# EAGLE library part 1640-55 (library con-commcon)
COMPACT PCI TYPE C - 55 PINS 2mm HARD METRIC SOCKETS
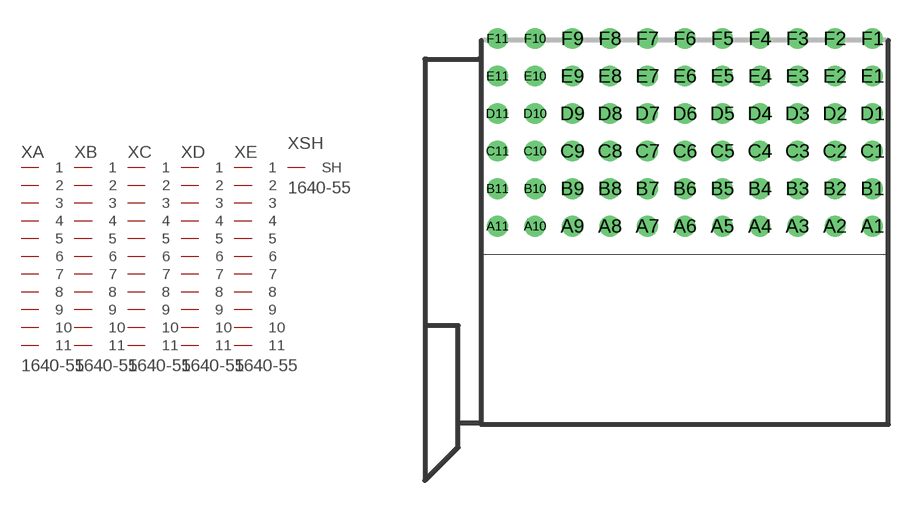
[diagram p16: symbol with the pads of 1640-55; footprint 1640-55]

Designator prefix X; gates A=PIN11 B=PIN11 C=PIN11 D=PIN11 E=PIN11 SH=SHIELD

## 1640-55 (OC_FARNELL: unknown; OC_NEWARK: unknown)  [1640-55]
A1  A:1  pas
A2  A:2  pas
A3  A:3  pas
A4  A:4  pas
A5  A:5  pas
A6  A:6  pas
A7  A:7  pas
A8  A:8  pas
A9  A:9  pas
A10  A:10  pas
A11  A:11  pas
B1  B:1  pas
B2  B:2  pas
B3  B:3  pas
B4  B:4  pas
B5  B:5  pas
B6  B:6  pas
B7  B:7  pas
B8  B:8  pas
B9  B:9  pas
B10  B:10  pas
B11  B:11  pas
C1  C:1  pas
C2  C:2  pas
C3  C:3  pas
C4  C:4  pas
C5  C:5  pas
C6  C:6  pas
C7  C:7  pas
C8  C:8  pas
C9  C:9  pas
C10  C:10  pas
C11  C:11  pas
D1  D:1  pas
D2  D:2  pas
D3  D:3  pas
D4  D:4  pas
D5  D:5  pas
D6  D:6  pas
D7  D:7  pas
D8  D:8  pas
D9  D:9  pas
D10  D:10  pas
D11  D:11  pas
E1  E:1  pas
E2  E:2  pas
E3  E:3  pas
E4  E:4  pas
E5  E:5  pas
E6  E:6  pas
E7  E:7  pas
E8  E:8  pas
E9  E:9  pas
E10  E:10  pas
E11  E:11  pas
F1  SH:SH  pas

## Footprint 1640-55 (pad centres in mm)
COMPACT PCI TYPE C - 55 PINS 2mm HARD METRIC SOCKETS
drill 0.6 round: A1 10,1.27; A2 8,1.27; A3 6,1.27; A4 4,1.27; A5 2,1.27; A6 0,1.27; A7 -2,1.27; A8 -4,1.27; A9 -6,1.27; A10 -8,1.27; A11 -10,1.27; B1 10,3.27; B2 8,3.27; B3 6,3.27; B4 4,3.27; B5 2,3.27; B6 0,3.27; B7 -2,3.27; B8 -4,3.27; B9 -6,3.27; B10 -8,3.27; B11 -10,3.27; C1 10,5.27; C2 8,5.27; C3 6,5.27; C4 4,5.27; C5 2,5.27; C6 0,5.27; C7 -2,5.27; C8 -4,5.27; C9 -6,5.27; C10 -8,5.27; C11 -10,5.27; D1 10,7.27; D2 8,7.27; D3 6,7.27; D4 4,7.27; D5 2,7.27; D6 0,7.27; D7 -2,7.27; D8 -4,7.27; D9 -6,7.27; D10 -8,7.27; D11 -10,7.27; E1 10,9.27; E2 8,9.27; E3 6,9.27; E4 4,9.27; E5 2,9.27; E6 0,9.27; E7 -2,9.27; E8 -4,9.27; E9 -6,9.27; E10 -8,9.27; E11 -10,9.27; F1 10,11.27; F2 8,11.27; F3 6,11.27; F4 4,11.27; F5 2,11.27; F6 0,11.27; F7 -2,11.27; F8 -4,11.27; F9 -6,11.27; F10 -8,11.27; F11 -10,11.27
